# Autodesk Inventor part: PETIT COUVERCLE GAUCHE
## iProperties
Created: 2004-11
Part Number: PETIT COUVERCLE GAUCHE
Document SubType Name: Modeling
Designer: Bruno
Manufacturer: Standard
Standards Organization: Custom
Author: Bruno
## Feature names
1. Base1
